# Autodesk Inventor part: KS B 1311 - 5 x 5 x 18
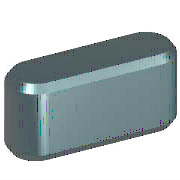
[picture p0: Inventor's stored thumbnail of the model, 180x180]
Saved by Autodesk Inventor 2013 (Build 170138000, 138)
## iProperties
IsCustomPart: 0
Created: 2009-02
Part Number: KS B 1311 - 5 x 5 x 18
Material: 강, 연강
Description: 키 및 해당 키홈
Document SubType Name: Modeling
Standard: KS B 1311
Designer: KYOUNG IL JANG
Standards Organization: KS
Language: ko-KR
Size Designation: 5 x 5 x 18
Categories: <MemberInstance><Categories><Category DisplayName="샤프트 부품" InternalName="7f7aeb1f-a693-4053-b835-cee3144e0d98" Mnemonic="SHFT"><Category DisplayName="키" Interna
Density: 1 g/cm^3
Author: KYOUNG IL JANG
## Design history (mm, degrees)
workplane "Work Plane1"
workplane "Work Plane2"
sketch "스케치1"
  geometry: L1 (2.5, 2.5)-(15.5, 2.5); L2 (15.5, -2.5)-(2.5, -2.5); L3 (0, 9.4)-(0, -7.4) reference; L4 (-5, 0)-(30, 0) reference; L5 (18, 0)-(18, 7); A1 r 2.5 centre (2.5, 0) between (2.5, 2.5) and (2.5, -2.5); A2 r 2.5 centre (15.5, 0) between (15.5, -2.5) and (15.5, 2.5)
  constraints: 6 end point, 5 point on circle, 4 tangent, 3 point on line, 2 centre point, 1 horizontal, 1 parallel, 1 perpendicular
  dimensions: "d0" = 2.5 radius of A1 (= 0.5 x PB); "d13" = 2.5 radius of A2 (= 0.5 x PB); "d14" = 18 distance between parallel lines of L5 L3 (= NLG)
extrude "본체1" new body sketch "스케치1" taper "d3" = 0 deg; stored distance "d4" = 10
workplane "Work Plane3"
body "Solid1"
chamfer "모따기1" distance "d8" = 0.4 (= PHH); stored, may be unused: second distance "d9" = 0.4 (= PHH), angle "d15" = 45 deg
other parameters: "d1" = -3 (= -PNT), "d2" = 2 (= PH - PNT), "NLG" = 18 [user parameter; used in 3 equation terms], "PB" = 5 [user parameter; used in 2 equation terms], "PNT" = 3 [user parameter; used in 2 equation terms], "PH" = 5 [user parameter; used in 1 equation term], "PHH" = 0.4 [user parameter; used in 2 equation terms], "d10" = 0, "d16" = 0, "d17" = 0, "d18" = 0, "WDMIN" = 12 [user parameter], "PLB2" = 18 (= NLG) [user parameter], "WDMAX" = 17 [user parameter], "PLB1" = 18 (= NLG) [user parameter], "RR" = 0.16 [user parameter], "PUEB" = 2.3 [user parameter]
